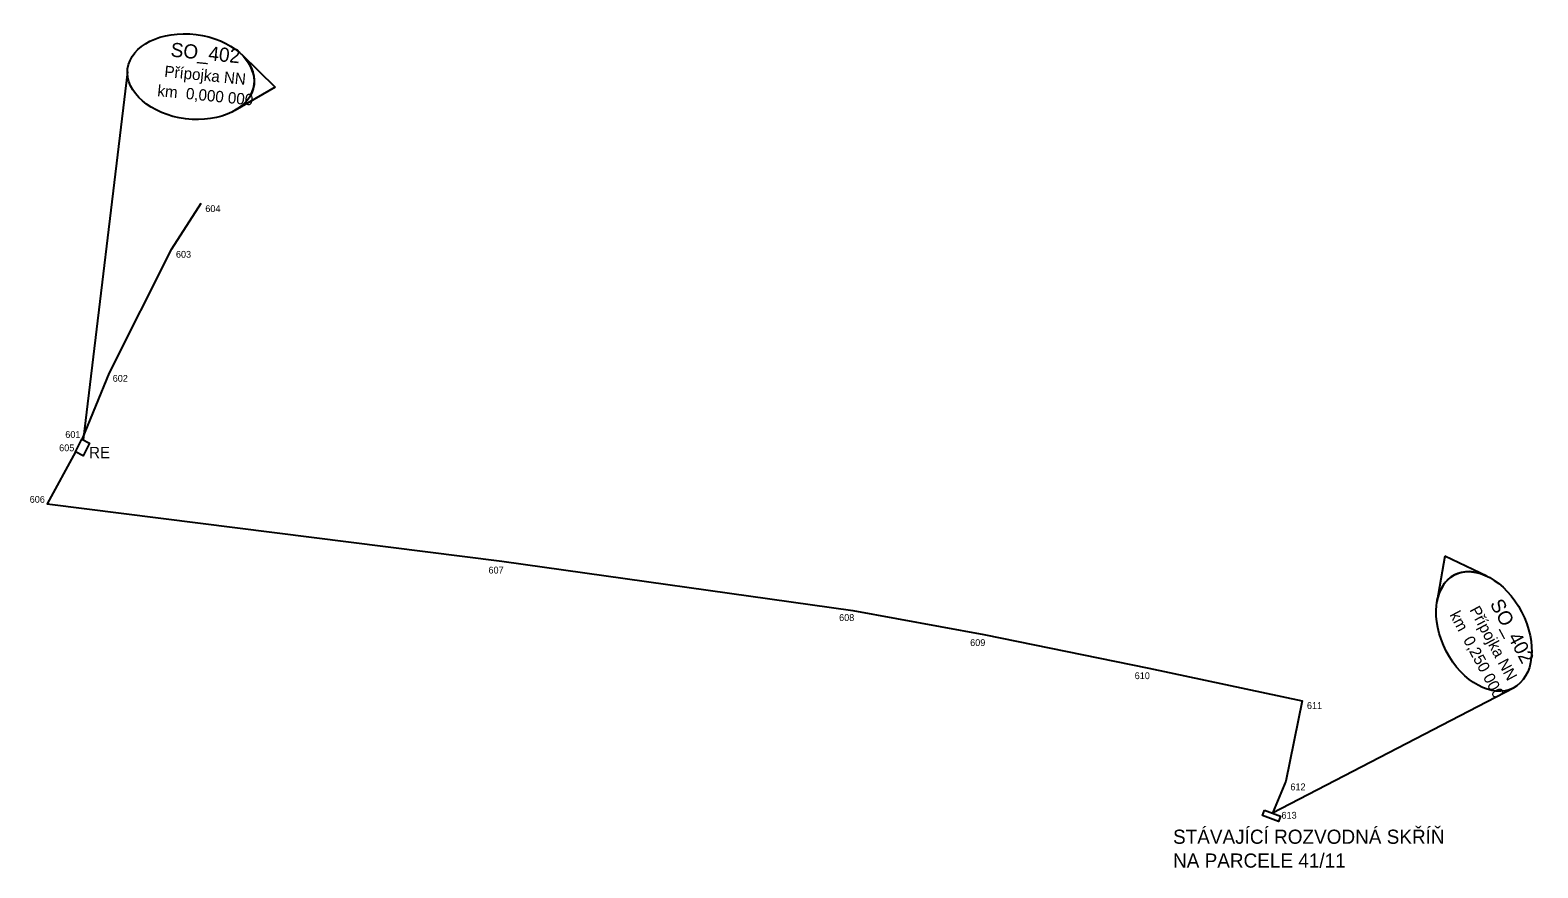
# Model space of a CAD drawing. Extents: x -743162 to -742896, y -1127156 to -1127008.
import ezdxf

# ---------------------------------------------------------------- set-up
doc = ezdxf.new("R2010")
doc.units = 0
for name, color, linetype in [('_Násyp', 7, 'Continuous'), ('_TRASA_vedení kabelu_CEZ', 7, 'Continuous'), ('bublina_fialová_čára_tenká', 7, 'Continuous'), ('bublina_růžová_230_čára_tenká', 7, 'Continuous'), ('bublina_růžová_230_čára_tučná', 7, 'Continuous'), ('křížky', 7, 'Continuous'), ('Vrstva 60', 7, 'Continuous')]:
    doc.layers.add(name, color=color, linetype=linetype)

# ---------------------------------------------------------------- blocks, each defined once
blk = doc.blocks.new('POINT_DISPLAY')
blk.add_line((0, 0), (0, 0))

msp = doc.modelspace()

# ---------------------------------------------------------------- linework, layer by layer
at = {"layer": '_TRASA_vedení kabelu_CEZ'}
for points in [[(-743153.07, -1127080.41), (-743148.26, -1127068.65), (-743137.26, -1127046.76), (-743132.07, -1127038.68)], [(-743154.26, -1127082.61), (-743159.25, -1127091.79), (-743078.98, -1127101.9), (-743017.04, -1127110.61), (-742993.93, -1127114.82), (-742964.82, -1127120.76), (-742937.74, -1127126.54), (-742940.65, -1127140.7), (-742943, -1127146.4)]]:
    msp.add_lwpolyline(points, dxfattribs=at)
for points in [[(-743154.26, -1127082.61), (-743153.14, -1127080.37), (-743151.8, -1127081.04), (-743152.91, -1127083.28)], [(-742944.4, -1127145.87), (-742941.59, -1127146.92), (-742941.94, -1127147.86), (-742944.75, -1127146.81)]]:
    msp.add_lwpolyline(points, close=True, dxfattribs=at)
at = {"layer": 'bublina_fialová_čára_tenká'}
msp.add_line((-743145.09, -1127015.48), (-743152.93, -1127080.48), dxfattribs=at)
at = {"layer": 'bublina_růžová_230_čára_tenká'}
msp.add_line((-742900.48, -1127124.28), (-742943, -1127146.4), dxfattribs=at)
at = {"layer": 'bublina_růžová_230_čára_tučná'}
for p, q in [((-743124.92, -1127012.47), (-743119, -1127018.23)), ((-743124.92, -1127012.47), (-743119, -1127018.23)), ((-743119, -1127018.23), (-743126.16, -1127022.35)), ((-743119, -1127018.23), (-743126.16, -1127022.35)), ((-742912.6, -1127100.99), (-742913.98, -1127109.13)), ((-742912.6, -1127100.99), (-742913.98, -1127109.13)), ((-742905.14, -1127104.53), (-742912.6, -1127100.99)), ((-742905.14, -1127104.53), (-742912.6, -1127100.99))]:
    msp.add_line(p, q, dxfattribs=at)
for centre, major_axis in [((-743133.89, -1127016.36), (-11.16, 1.4)), ((-742905.68, -1127114.3), (5.19, -9.98))]:
    msp.add_ellipse(centre, major_axis=major_axis, ratio=0.666667, dxfattribs=at)
for centre, major_axis in [((-743133.89, -1127016.36), (11.16, -1.4)), ((-742905.68, -1127114.3), (-5.19, 9.98))]:
    msp.add_ellipse(centre, major_axis=major_axis, ratio=0.666473, start_param=5.557317, end_param=7.009053, dxfattribs=at)
at = {"layer": 'Vrstva 60'}
for p, q in [((-743132.07, -1127038.68), (-743132.07, -1127038.68)), ((-743137.26, -1127046.76), (-743137.26, -1127046.76)), ((-743148.26, -1127068.65), (-743148.26, -1127068.65)), ((-743153.07, -1127080.41), (-743153.07, -1127080.41)), ((-743154.26, -1127082.61), (-743154.26, -1127082.61)), ((-743159.25, -1127091.79), (-743159.25, -1127091.79)), ((-743078.98, -1127101.9), (-743078.98, -1127101.9)), ((-743017.04, -1127110.61), (-743017.04, -1127110.61)), ((-742993.93, -1127114.82), (-742993.93, -1127114.82)), ((-742964.82, -1127120.76), (-742964.82, -1127120.76)), ((-742937.74, -1127126.54), (-742937.74, -1127126.54)), ((-742940.65, -1127140.7), (-742940.65, -1127140.7)), ((-742943, -1127146.4), (-742943, -1127146.4))]:
    msp.add_line(p, q, dxfattribs=at)

# ---------------------------------------------------------------- block references
at = {"layer": 'křížky', "xscale": 10, "yscale": 10, "rotation": 61.14491455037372}
for p in [(-743132.07, -1127038.68), (-743137.26, -1127046.76), (-743148.26, -1127068.65), (-743153.07, -1127080.41), (-743154.26, -1127082.61), (-743159.25, -1127091.79), (-743078.98, -1127101.9), (-743017.04, -1127110.61), (-742993.93, -1127114.82), (-742964.82, -1127120.76), (-742937.74, -1127126.54), (-742940.65, -1127140.7), (-742943, -1127146.4)]:
    msp.add_blockref('POINT_DISPLAY', p, dxfattribs=at)

# ---------------------------------------------------------------- texts
at = {"layer": '_Násyp'}
for s, height, rotation, p in [('SO_402', 2.5, 354.3558, (-743137.54, -1127012.8)), ('Přípojka NN', 2, 354.3558, (-743138.64, -1127016.39)), ('km  0,000 000', 2, 354.3558, (-743139.87, -1127019.79)), ('km  0,250 000', 2, 298.159, (-742911.78, -1127111.35)), ('Přípojka NN', 2, 298.159, (-742908.27, -1127110.47)), ('SO_402', 2.5, 298.159, (-742904.68, -1127109.39))]:
    msp.add_text(s, height=height, rotation=rotation, dxfattribs=at).set_placement(p)
at = {"layer": '_TRASA_vedení kabelu_CEZ'}
for s, height, p in [('RE', 2, (-743151.87, -1127083.71)), ('STÁVAJÍCÍ ROZVODNÁ SKŘÍŇ ', 2.5, (-742960.54, -1127151.78)), ('NA PARCELE 41/11', 2.5, (-742960.54, -1127155.99))]:
    msp.add_text(s, height=height, dxfattribs=at).set_placement(p)
at = {"layer": 'Vrstva 60'}
for s, p in [('604', (-743131.35, -1127040.26)), ('603', (-743136.53, -1127048.32)), ('602', (-743147.69, -1127070.22)), ('601', (-743156.06, -1127080.13)), ('605', (-743157.14, -1127082.48)), ('606', (-743162.34, -1127091.58)), ('607', (-743081.37, -1127104.07)), ('608', (-743019.48, -1127112.44)), ('609', (-742996.35, -1127116.86)), ('610', (-742967.31, -1127122.71)), ('611', (-742936.91, -1127127.97)), ('612', (-742939.83, -1127142.33)), ('613', (-742941.4, -1127147.34))]:
    msp.add_text(s, height=1.2, dxfattribs=at).set_placement(p)

doc.saveas('drawing.dxf')
